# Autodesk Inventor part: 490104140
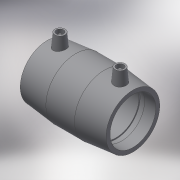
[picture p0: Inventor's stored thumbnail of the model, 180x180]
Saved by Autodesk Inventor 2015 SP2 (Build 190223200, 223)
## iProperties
Created: 2017-06
Part Number: 490104140
Material: Generic
Description: PLASSON COUPLER 140-140
Document SubType Name: Modeling
Designer: KIM
Mass: 1248.69 g
Surface Area: 1954.74 cm^2
Volume: 1248.69 cm^3
Density: 1 g/cm^3
Appearance: Default
Author: KIM
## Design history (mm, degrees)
derived "490104.ipt"
feature "Solid1::490104.ipt"
tag "TaggingFeature1"
body "Solid1"
other parameters: "d0" = 183, "d2" = 174, "d4" = 61, "d5" = 156.6, "d6" = 133, "d8" = 168 deg, "d10" = 36, "d11" = 12, "d13" = 183, "d14" = 17.6296, "d17" = 133, "d19" = 3.52592, "d20" = 168 deg, "d22" = 163.56, "d23" = 174, "d24" = 158.6532, "d25" = 135 deg, "d26" = 73.2, "d27" = 135 deg, "d29" = 97, "d30" = 14, "d31" = 64.05, "d34" = 5 deg, "d35" = 15, "d39" = 5 deg, "d41" = 4, "d42" = 14, "d43" = 0, "d45" = 4, "d46" = 14, "d47" = 0, "d48" = 3, "d49" = 0, "d50" = 3, "d51" = 0, "d52" = 26.1, "d53" = 6.525, "L_" = 183, "D_" = 174, "A_" = 97, "d_2" = 12
